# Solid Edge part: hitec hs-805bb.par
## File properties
Author: nakano
Template: iso metric part.par
Last saved by: nakano
Revision: 7
Application: Solid Edge
Density: 1236.46483555047 kg/m^3
Accuracy: 0.990
Username: nakano
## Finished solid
Body 1: solid body, 171 faces, 425 edges, 262 vertices.
  Faces by surface: plane 143, cylinder 20, torus 6, cone 2
  Edges by curve: line 329, circle 54, intersection 30, ellipse 12
Bounding box of the edges (mm; curved faces can reach further): 29.972 x 82.000 x 69.000, from (-14.986, -41, 0) to (14.986, 41, 69).
Cylindrical faces by radius (mm): R1.25 x1, R1.3 x1, R1.4142 x5, R2 x10, R5 x1, R7 x1, R11.3 x1
Conical faces (half-angle, radius in mm at the cone's reference point): 45 deg R0 x1, 45 deg R4.5 x1
Toroidal faces (ring radius, tube radius in mm): R1.1142 r0.3 x4, R1.2 r0.1 x1, R1.3142 r0.1 x1
Planar faces by outward normal: +x 24, +y 23, +z 8, -x 23, -y 25, -z 26, oblique 14
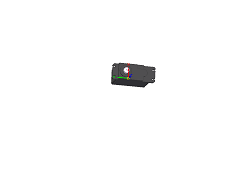
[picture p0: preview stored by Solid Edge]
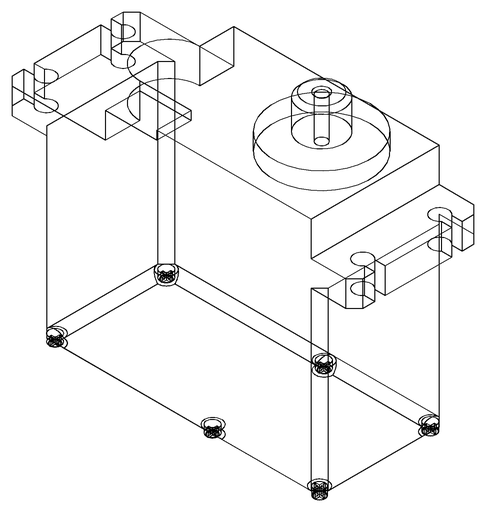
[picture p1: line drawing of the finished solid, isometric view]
